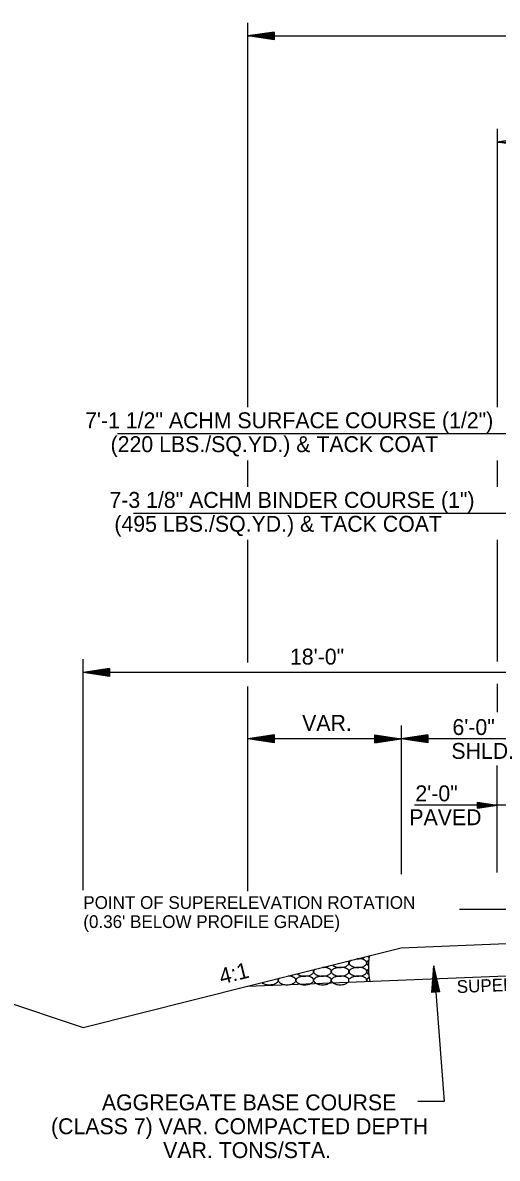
# Model space of a CAD drawing. Extents: x 2263886 to 2266026, y -3122850 to -3121850.
# Drawn here: x 2265563.48 to 2265581.37, y -3122515.03 to -3122472.22 of the extents above; entities that cross this region are included whole.
import ezdxf

# ---------------------------------------------------------------- set-up
doc = ezdxf.new("R2010")
doc.units = 0
doc.layers.add('R_Border Prem', color=7, linetype='Continuous')

msp = doc.modelspace()

# ---------------------------------------------------------------- linework, layer by layer
at = {"layer": 'R_Border Prem'}
for p, q in [((2265571.962, -3122486.717), (2265571.962, -3122472.217)), ((2265572.962, -3122472.567), (2265571.962, -3122472.717)), ((2265572.962, -3122472.567), (2265572.962, -3122472.867)), ((2265571.962, -3122472.717), (2265632.576, -3122472.717)), ((2265572.962, -3122472.867), (2265571.962, -3122472.717)), ((2265572.962, -3122472.592), (2265572.129, -3122472.717)), ((2265572.962, -3122472.842), (2265572.129, -3122472.717)), ((2265572.962, -3122472.617), (2265572.301, -3122472.717)), ((2265572.962, -3122472.816), (2265572.301, -3122472.717)), ((2265572.962, -3122472.642), (2265572.467, -3122472.717)), ((2265572.962, -3122472.791), (2265572.467, -3122472.717)), ((2265572.962, -3122472.668), (2265572.637, -3122472.717)), ((2265572.962, -3122472.766), (2265572.637, -3122472.717)), ((2265572.962, -3122472.693), (2265572.804, -3122472.717)), ((2265572.962, -3122472.74), (2265572.804, -3122472.717)), ((2265581.369, -3122476.217), (2265581.369, -3122486.717)), ((2265582.369, -3122476.567), (2265581.369, -3122476.717)), ((2265581.369, -3122476.717), (2265622.13, -3122476.717)), ((2265582.369, -3122476.867), (2265581.369, -3122476.717)), ((2265583.623, -3122487.72), (2265567.047, -3122487.72)), ((2265571.962, -3122489.717), (2265571.962, -3122488.717)), ((2265581.369, -3122488.717), (2265581.369, -3122489.717)), ((2265583.518, -3122490.72), (2265567.654, -3122490.72)), ((2265571.962, -3122496.338), (2265571.962, -3122491.717)), ((2265581.369, -3122491.717), (2265581.369, -3122494.717)), ((2265581.369, -3122494.717), (2265581.369, -3122496.297)), ((2265565.75, -3122504.917), (2265565.75, -3122496.217)), ((2265566.75, -3122496.567), (2265565.75, -3122496.717)), ((2265566.75, -3122496.567), (2265566.75, -3122496.867)), ((2265583.75, -3122496.717), (2265565.75, -3122496.717)), ((2265566.75, -3122496.867), (2265565.75, -3122496.717)), ((2265566.75, -3122496.592), (2265565.917, -3122496.717)), ((2265566.75, -3122496.842), (2265565.917, -3122496.717)), ((2265566.75, -3122496.617), (2265566.089, -3122496.717)), ((2265566.75, -3122496.816), (2265566.089, -3122496.717)), ((2265566.75, -3122496.642), (2265566.255, -3122496.717)), ((2265566.75, -3122496.791), (2265566.255, -3122496.717)), ((2265566.75, -3122496.668), (2265566.425, -3122496.717)), ((2265566.75, -3122496.766), (2265566.425, -3122496.717)), ((2265566.75, -3122496.693), (2265566.592, -3122496.717)), ((2265566.75, -3122496.74), (2265566.592, -3122496.717)), ((2265571.962, -3122504.954), (2265571.962, -3122497.248)), ((2265581.369, -3122497.137), (2265581.369, -3122498.217)), ((2265572.962, -3122499.067), (2265571.962, -3122499.217)), ((2265572.962, -3122499.092), (2265572.129, -3122499.217)), ((2265572.962, -3122499.117), (2265572.301, -3122499.217)), ((2265572.962, -3122499.067), (2265572.962, -3122499.367)), ((2265576.75, -3122499.067), (2265577.75, -3122499.217)), ((2265576.75, -3122499.367), (2265576.75, -3122499.067)), ((2265576.75, -3122499.092), (2265577.583, -3122499.217)), ((2265576.75, -3122499.117), (2265577.411, -3122499.217)), ((2265577.75, -3122498.717), (2265577.75, -3122504.317)), ((2265578.75, -3122499.067), (2265577.75, -3122499.217)), ((2265578.75, -3122499.092), (2265577.917, -3122499.217)), ((2265578.75, -3122499.117), (2265578.089, -3122499.217)), ((2265578.75, -3122499.067), (2265578.75, -3122499.367)), ((2265572.962, -3122499.367), (2265571.962, -3122499.217)), ((2265577.75, -3122499.217), (2265571.962, -3122499.217)), ((2265572.962, -3122499.342), (2265572.129, -3122499.217)), ((2265572.962, -3122499.316), (2265572.301, -3122499.217)), ((2265572.962, -3122499.142), (2265572.467, -3122499.217)), ((2265572.962, -3122499.291), (2265572.467, -3122499.217)), ((2265572.962, -3122499.168), (2265572.637, -3122499.217)), ((2265572.962, -3122499.266), (2265572.637, -3122499.217)), ((2265572.962, -3122499.193), (2265572.804, -3122499.217)), ((2265572.962, -3122499.24), (2265572.804, -3122499.217)), ((2265576.75, -3122499.142), (2265577.244, -3122499.217)), ((2265576.75, -3122499.168), (2265577.075, -3122499.217)), ((2265576.75, -3122499.193), (2265576.908, -3122499.217)), ((2265576.75, -3122499.367), (2265577.75, -3122499.217)), ((2265576.75, -3122499.265), (2265577.075, -3122499.217)), ((2265576.75, -3122499.316), (2265577.411, -3122499.217)), ((2265576.75, -3122499.342), (2265577.583, -3122499.217)), ((2265576.75, -3122499.291), (2265577.244, -3122499.217)), ((2265576.75, -3122499.24), (2265576.908, -3122499.217)), ((2265578.75, -3122499.367), (2265577.75, -3122499.217)), ((2265583.75, -3122499.217), (2265577.75, -3122499.217)), ((2265578.75, -3122499.342), (2265577.917, -3122499.217)), ((2265578.75, -3122499.316), (2265578.089, -3122499.217)), ((2265578.75, -3122499.142), (2265578.255, -3122499.217)), ((2265578.75, -3122499.291), (2265578.255, -3122499.217)), ((2265578.75, -3122499.168), (2265578.425, -3122499.217)), ((2265578.75, -3122499.266), (2265578.425, -3122499.217)), ((2265578.75, -3122499.193), (2265578.592, -3122499.217)), ((2265578.75, -3122499.24), (2265578.592, -3122499.217)), ((2265581.369, -3122504.251), (2265581.369, -3122500.217)), ((2265580.619, -3122501.604), (2265581.369, -3122501.717)), ((2265580.619, -3122501.829), (2265580.619, -3122501.604)), ((2265580.619, -3122501.623), (2265581.244, -3122501.717)), ((2265580.619, -3122501.642), (2265581.115, -3122501.717)), ((2265580.619, -3122501.661), (2265580.99, -3122501.717)), ((2265580.619, -3122501.68), (2265580.863, -3122501.717)), ((2265580.619, -3122501.699), (2265580.738, -3122501.717)), ((2265583.75, -3122501.717), (2265578.242, -3122501.717)), ((2265580.619, -3122501.829), (2265581.369, -3122501.717)), ((2265580.619, -3122501.753), (2265580.863, -3122501.717)), ((2265580.619, -3122501.791), (2265581.115, -3122501.717)), ((2265580.619, -3122501.81), (2265581.244, -3122501.717)), ((2265580.619, -3122501.773), (2265580.99, -3122501.717)), ((2265580.619, -3122501.734), (2265580.738, -3122501.717)), ((2265582.009, -3122505.651), (2265579.95, -3122505.651)), ((2265555.75, -3122506.763), (2265565.75, -3122510.097)), ((2265572.105, -3122508.508), (2265577.75, -3122507.097)), ((2265577.75, -3122507.097), (2265583.745, -3122506.857)), ((2265571.962, -3122508.544), (2265590.987, -3122507.782)), ((2265578.899, -3122508.782), (2265578.971, -3122507.774)), ((2265578.924, -3122508.78), (2265578.984, -3122507.94)), ((2265578.949, -3122508.778), (2265578.997, -3122508.112)), ((2265578.971, -3122507.774), (2265579.368, -3122512.886)), ((2265579.198, -3122508.759), (2265578.971, -3122507.774)), ((2265579.173, -3122508.761), (2265578.984, -3122507.94)), ((2265579.147, -3122508.763), (2265578.997, -3122508.112)), ((2265565.75, -3122510.097), (2265572.105, -3122508.508)), ((2265578.974, -3122508.777), (2265579.01, -3122508.278)), ((2265578.999, -3122508.775), (2265579.023, -3122508.447)), ((2265579.123, -3122508.765), (2265579.01, -3122508.278)), ((2265579.097, -3122508.767), (2265579.023, -3122508.447)), ((2265579.198, -3122508.759), (2265578.899, -3122508.782)), ((2265579.025, -3122508.773), (2265579.036, -3122508.613)), ((2265579.072, -3122508.769), (2265579.036, -3122508.613)), ((2265579.368, -3122512.886), (2265578.368, -3122512.886))]:
    msp.add_line(p, q, dxfattribs=at)
msp.add_arc((2265579.507, -3122507.797), 3, 172.4161, 190.8159, dxfattribs=at)
for points in [[(2265575.153, -3122507.746), (2265575.159, -3122507.75), (2265575.172, -3122507.759), (2265575.184, -3122507.778), (2265575.211, -3122507.783), (2265575.246, -3122507.804), (2265575.308, -3122507.82), (2265575.388, -3122507.837), (2265575.483, -3122507.836), (2265575.581, -3122507.822), (2265575.671, -3122507.798), (2265575.73, -3122507.752), (2265575.772, -3122507.716), (2265575.777, -3122507.677), (2265575.778, -3122507.644), (2265575.77, -3122507.616), (2265575.759, -3122507.602), (2265575.753, -3122507.596), (2265575.753, -3122507.596)], [(2265575.804, -3122507.607), (2265575.798, -3122507.613), (2265575.79, -3122507.628), (2265575.784, -3122507.651), (2265575.774, -3122507.672), (2265575.784, -3122507.696), (2265575.793, -3122507.717), (2265575.812, -3122507.74), (2265575.837, -3122507.755), (2265575.852, -3122507.778), (2265575.879, -3122507.783), (2265575.913, -3122507.804), (2265575.976, -3122507.82), (2265576.056, -3122507.837), (2265576.151, -3122507.836), (2265576.249, -3122507.822), (2265576.339, -3122507.798), (2265576.398, -3122507.752), (2265576.44, -3122507.716), (2265576.445, -3122507.677), (2265576.445, -3122507.644), (2265576.438, -3122507.616), (2265576.421, -3122507.596), (2265576.404, -3122507.58), (2265576.378, -3122507.569), (2265576.355, -3122507.55), (2265576.323, -3122507.539), (2265576.283, -3122507.519), (2265576.216, -3122507.515), (2265576.146, -3122507.51), (2265576.096, -3122507.514), (2265576.075, -3122507.515), (2265576.074, -3122507.515)], [(2265575.855, -3122507.57), (2265575.853, -3122507.571), (2265575.839, -3122507.58), (2265575.821, -3122507.596), (2265575.803, -3122507.608), (2265575.798, -3122507.613)], [(2265576.1, -3122507.509), (2265576.116, -3122507.509), (2265576.165, -3122507.507), (2265576.249, -3122507.496), (2265576.329, -3122507.473), (2265576.369, -3122507.447), (2265576.38, -3122507.439)], [(2265576.472, -3122507.607), (2265576.466, -3122507.613), (2265576.458, -3122507.628), (2265576.452, -3122507.651), (2265576.441, -3122507.672), (2265576.452, -3122507.696), (2265576.461, -3122507.717), (2265576.48, -3122507.74), (2265576.498, -3122507.752), (2265576.508, -3122507.761), (2265576.508, -3122507.761)], [(2265576.516, -3122507.575), (2265576.504, -3122507.582), (2265576.488, -3122507.596), (2265576.471, -3122507.608), (2265576.466, -3122507.613)], [(2265576.481, -3122507.414), (2265576.489, -3122507.42), (2265576.505, -3122507.43), (2265576.518, -3122507.446), (2265576.527, -3122507.451), (2265576.528, -3122507.451)], [(2265573.512, -3122508.156), (2265573.533, -3122508.153), (2265573.585, -3122508.145), (2265573.633, -3122508.131), (2265573.661, -3122508.119)], [(2265573.825, -3122508.078), (2265573.828, -3122508.08), (2265573.838, -3122508.087), (2265573.849, -3122508.104), (2265573.876, -3122508.11), (2265573.91, -3122508.13), (2265573.972, -3122508.146), (2265574.053, -3122508.163), (2265574.147, -3122508.162), (2265574.246, -3122508.148), (2265574.335, -3122508.124), (2265574.395, -3122508.078), (2265574.436, -3122508.042), (2265574.441, -3122508.003), (2265574.442, -3122507.97), (2265574.435, -3122507.944), (2265574.426, -3122507.932), (2265574.423, -3122507.928)], [(2265574.469, -3122507.934), (2265574.462, -3122507.939), (2265574.455, -3122507.954), (2265574.448, -3122507.977), (2265574.438, -3122507.998), (2265574.448, -3122508.022), (2265574.457, -3122508.043), (2265574.476, -3122508.067), (2265574.501, -3122508.081), (2265574.517, -3122508.104), (2265574.543, -3122508.11), (2265574.578, -3122508.13), (2265574.64, -3122508.146), (2265574.72, -3122508.163), (2265574.815, -3122508.162), (2265574.913, -3122508.148), (2265575.003, -3122508.124), (2265575.062, -3122508.078), (2265575.104, -3122508.042), (2265575.109, -3122508.003), (2265575.11, -3122507.97), (2265575.102, -3122507.942), (2265575.085, -3122507.922), (2265575.068, -3122507.906), (2265575.042, -3122507.895), (2265575.02, -3122507.877), (2265574.987, -3122507.865), (2265574.947, -3122507.845), (2265574.881, -3122507.841), (2265574.824, -3122507.836), (2265574.789, -3122507.838), (2265574.782, -3122507.839)], [(2265574.501, -3122507.909), (2265574.493, -3122507.914), (2265574.48, -3122507.925), (2265574.467, -3122507.934), (2265574.463, -3122507.94)], [(2265574.799, -3122507.834), (2265574.804, -3122507.834), (2265574.841, -3122507.832), (2265574.913, -3122507.822), (2265574.985, -3122507.801), (2265575.021, -3122507.781), (2265575.027, -3122507.777)], [(2265575.136, -3122507.934), (2265575.13, -3122507.939), (2265575.123, -3122507.954), (2265575.116, -3122507.977), (2265575.106, -3122507.998), (2265575.116, -3122508.022), (2265575.125, -3122508.043), (2265575.144, -3122508.067), (2265575.169, -3122508.081), (2265575.184, -3122508.104), (2265575.211, -3122508.11), (2265575.246, -3122508.13), (2265575.308, -3122508.146), (2265575.388, -3122508.163), (2265575.483, -3122508.162), (2265575.581, -3122508.148), (2265575.671, -3122508.124), (2265575.73, -3122508.078), (2265575.772, -3122508.042), (2265575.777, -3122508.003), (2265575.778, -3122507.97), (2265575.77, -3122507.942), (2265575.753, -3122507.922), (2265575.736, -3122507.906), (2265575.71, -3122507.895), (2265575.687, -3122507.877), (2265575.655, -3122507.865), (2265575.615, -3122507.845), (2265575.549, -3122507.841), (2265575.478, -3122507.836), (2265575.408, -3122507.843), (2265575.353, -3122507.843), (2265575.306, -3122507.857), (2265575.261, -3122507.864), (2265575.218, -3122507.879), (2265575.179, -3122507.901), (2265575.153, -3122507.922), (2265575.135, -3122507.934), (2265575.13, -3122507.94)], [(2265575.804, -3122507.934), (2265575.798, -3122507.939), (2265575.79, -3122507.954), (2265575.784, -3122507.977), (2265575.774, -3122507.998), (2265575.784, -3122508.022), (2265575.793, -3122508.043), (2265575.812, -3122508.067), (2265575.837, -3122508.081), (2265575.852, -3122508.104), (2265575.879, -3122508.11), (2265575.913, -3122508.13), (2265575.976, -3122508.146), (2265576.056, -3122508.163), (2265576.151, -3122508.162), (2265576.249, -3122508.148), (2265576.339, -3122508.124), (2265576.398, -3122508.078), (2265576.44, -3122508.042), (2265576.445, -3122508.003), (2265576.445, -3122507.97), (2265576.438, -3122507.942), (2265576.421, -3122507.922), (2265576.404, -3122507.906), (2265576.378, -3122507.895), (2265576.355, -3122507.877), (2265576.323, -3122507.865), (2265576.283, -3122507.845), (2265576.216, -3122507.841), (2265576.146, -3122507.836), (2265576.076, -3122507.843), (2265576.021, -3122507.843), (2265575.974, -3122507.857), (2265575.929, -3122507.864), (2265575.886, -3122507.879), (2265575.847, -3122507.901), (2265575.821, -3122507.922), (2265575.803, -3122507.934), (2265575.798, -3122507.94)], [(2265576.472, -3122507.934), (2265576.466, -3122507.939), (2265576.458, -3122507.954), (2265576.452, -3122507.977), (2265576.441, -3122507.998), (2265576.452, -3122508.022), (2265576.461, -3122508.043), (2265576.48, -3122508.067), (2265576.504, -3122508.081), (2265576.517, -3122508.096), (2265576.523, -3122508.101)], [(2265576.51, -3122507.905), (2265576.5, -3122507.911), (2265576.486, -3122507.923), (2265576.471, -3122507.934), (2265576.466, -3122507.94)], [(2265572.497, -3122508.41), (2265572.497, -3122508.41), (2265572.504, -3122508.416), (2265572.513, -3122508.431), (2265572.54, -3122508.436), (2265572.574, -3122508.456), (2265572.636, -3122508.473), (2265572.717, -3122508.489), (2265572.812, -3122508.488), (2265572.91, -3122508.475), (2265573, -3122508.45), (2265573.059, -3122508.404), (2265573.101, -3122508.368), (2265573.105, -3122508.33), (2265573.106, -3122508.296), (2265573.1, -3122508.274), (2265573.093, -3122508.263), (2265573.092, -3122508.261)], [(2265573.133, -3122508.26), (2265573.127, -3122508.265), (2265573.119, -3122508.28), (2265573.113, -3122508.304), (2265573.102, -3122508.324), (2265573.112, -3122508.348), (2265573.122, -3122508.369), (2265573.141, -3122508.393), (2265573.165, -3122508.407), (2265573.181, -3122508.431), (2265573.208, -3122508.436), (2265573.242, -3122508.456), (2265573.304, -3122508.473), (2265573.385, -3122508.489), (2265573.479, -3122508.488), (2265573.578, -3122508.475), (2265573.667, -3122508.45), (2265573.727, -3122508.404), (2265573.769, -3122508.368), (2265573.773, -3122508.33), (2265573.774, -3122508.296), (2265573.766, -3122508.268), (2265573.75, -3122508.249), (2265573.732, -3122508.232), (2265573.706, -3122508.221), (2265573.684, -3122508.203), (2265573.651, -3122508.191), (2265573.611, -3122508.171), (2265573.55, -3122508.168), (2265573.506, -3122508.163), (2265573.482, -3122508.163)], [(2265573.149, -3122508.247), (2265573.147, -3122508.248), (2265573.139, -3122508.254), (2265573.131, -3122508.26), (2265573.127, -3122508.266)], [(2265573.801, -3122508.26), (2265573.794, -3122508.265), (2265573.787, -3122508.28), (2265573.78, -3122508.304), (2265573.77, -3122508.324), (2265573.78, -3122508.348), (2265573.79, -3122508.369), (2265573.809, -3122508.393), (2265573.833, -3122508.407), (2265573.849, -3122508.431), (2265573.876, -3122508.436), (2265573.91, -3122508.456), (2265573.972, -3122508.473), (2265574.053, -3122508.489), (2265574.147, -3122508.488), (2265574.246, -3122508.475), (2265574.335, -3122508.45), (2265574.395, -3122508.404), (2265574.436, -3122508.368), (2265574.441, -3122508.33), (2265574.442, -3122508.296), (2265574.434, -3122508.268), (2265574.418, -3122508.249), (2265574.4, -3122508.232), (2265574.374, -3122508.221), (2265574.352, -3122508.203), (2265574.319, -3122508.191), (2265574.279, -3122508.171), (2265574.213, -3122508.167), (2265574.143, -3122508.162), (2265574.072, -3122508.169), (2265574.018, -3122508.17), (2265573.971, -3122508.183), (2265573.925, -3122508.19), (2265573.882, -3122508.206), (2265573.843, -3122508.227), (2265573.817, -3122508.248), (2265573.799, -3122508.26), (2265573.795, -3122508.266)], [(2265574.469, -3122508.26), (2265574.462, -3122508.265), (2265574.455, -3122508.28), (2265574.448, -3122508.304), (2265574.438, -3122508.324), (2265574.448, -3122508.348), (2265574.457, -3122508.369), (2265574.476, -3122508.393), (2265574.501, -3122508.407), (2265574.517, -3122508.431), (2265574.543, -3122508.436), (2265574.578, -3122508.456), (2265574.64, -3122508.473), (2265574.72, -3122508.489), (2265574.815, -3122508.488), (2265574.913, -3122508.475), (2265575.003, -3122508.45), (2265575.062, -3122508.404), (2265575.104, -3122508.368), (2265575.109, -3122508.33), (2265575.11, -3122508.296), (2265575.102, -3122508.268), (2265575.085, -3122508.249), (2265575.068, -3122508.232), (2265575.042, -3122508.221), (2265575.02, -3122508.203), (2265574.987, -3122508.191), (2265574.947, -3122508.171), (2265574.881, -3122508.167), (2265574.81, -3122508.162), (2265574.74, -3122508.169), (2265574.686, -3122508.17), (2265574.639, -3122508.183), (2265574.593, -3122508.19), (2265574.55, -3122508.206), (2265574.511, -3122508.227), (2265574.485, -3122508.248), (2265574.467, -3122508.26), (2265574.463, -3122508.266)], [(2265575.136, -3122508.26), (2265575.13, -3122508.265), (2265575.123, -3122508.28), (2265575.116, -3122508.304), (2265575.106, -3122508.324), (2265575.116, -3122508.348), (2265575.125, -3122508.369), (2265575.144, -3122508.393), (2265575.169, -3122508.407), (2265575.184, -3122508.431), (2265575.211, -3122508.436), (2265575.246, -3122508.456), (2265575.308, -3122508.473), (2265575.388, -3122508.489), (2265575.483, -3122508.488), (2265575.581, -3122508.475), (2265575.671, -3122508.45), (2265575.73, -3122508.404), (2265575.772, -3122508.368), (2265575.777, -3122508.33), (2265575.778, -3122508.296), (2265575.77, -3122508.268), (2265575.753, -3122508.249), (2265575.736, -3122508.232), (2265575.71, -3122508.221), (2265575.687, -3122508.203), (2265575.655, -3122508.191), (2265575.615, -3122508.171), (2265575.549, -3122508.167), (2265575.478, -3122508.162), (2265575.408, -3122508.169), (2265575.353, -3122508.17), (2265575.306, -3122508.183), (2265575.261, -3122508.19), (2265575.218, -3122508.206), (2265575.179, -3122508.227), (2265575.153, -3122508.248), (2265575.135, -3122508.26), (2265575.13, -3122508.266)], [(2265576.436, -3122508.365), (2265576.436, -3122508.363), (2265576.442, -3122508.352), (2265576.445, -3122508.33), (2265576.445, -3122508.296), (2265576.438, -3122508.268), (2265576.421, -3122508.249), (2265576.404, -3122508.232), (2265576.378, -3122508.221), (2265576.355, -3122508.203), (2265576.323, -3122508.191), (2265576.283, -3122508.171), (2265576.216, -3122508.167), (2265576.146, -3122508.162), (2265576.076, -3122508.169), (2265576.021, -3122508.17), (2265575.974, -3122508.183), (2265575.929, -3122508.19), (2265575.886, -3122508.206), (2265575.847, -3122508.227), (2265575.821, -3122508.248), (2265575.803, -3122508.26), (2265575.798, -3122508.266)], [(2265576.472, -3122508.26), (2265576.466, -3122508.265), (2265576.458, -3122508.28), (2265576.452, -3122508.304), (2265576.441, -3122508.324), (2265576.451, -3122508.346), (2265576.456, -3122508.357), (2265576.459, -3122508.364)], [(2265576.537, -3122508.215), (2265576.531, -3122508.218), (2265576.511, -3122508.229), (2265576.488, -3122508.248), (2265576.471, -3122508.26), (2265576.466, -3122508.266)]]:
    msp.add_open_spline(points, degree=3, dxfattribs=at)

# ---------------------------------------------------------------- texts
for s, height, p in [('7\'-1 1/2" ACHM SURFACE COURSE (1/2")', 0.6, (2265565.827, -3122487.507)), ('(220 LBS./SQ.YD.) & TACK COAT', 0.6, (2265566.789, -3122488.407)), ('7-3 1/8" ACHM BINDER COURSE (1")', 0.6, (2265566.745, -3122490.509)), ('(495 LBS./SQ.YD.) & TACK COAT', 0.6, (2265566.931, -3122491.409)), ('18\'-0"', 0.6, (2265573.552, -3122496.417)), ('6\'-0"', 0.6, (2265579.678, -3122499.072)), ('SHLD.', 0.6, (2265579.638, -3122499.972)), ('2\'-0"', 0.6, (2265578.281, -3122501.572)), ('PAVED', 0.6, (2265578.054, -3122502.472)), ('POINT OF SUPERELEVATION ROTATION', 0.48, (2265565.76, -3122505.629)), ("(0.36' BELOW PROFILE GRADE)", 0.48, (2265565.76, -3122506.349)), ('AGGREGATE BASE COURSE', 0.6, (2265566.46, -3122513.223)), ('(CLASS 7) VAR. COMPACTED DEPTH', 0.6, (2265564.542, -3122514.123)), ('VAR. TONS/STA.', 0.6, (2265568.77, -3122515.023))]:
    msp.add_text(s, height=height, dxfattribs=at).set_placement(p)
for s, height, rotation, p in [('VAR.', 0.6, 0, (2265574.011, -3122498.917)), ('4:1', 0.6, 14.0362, (2265570.971, -3122508.482)), ('SUPER. SLOPE', 0.48, 2.291, (2265579.85, -3122508.802))]:
    msp.add_text(s, height=height, rotation=rotation, dxfattribs=at).set_placement(p)

doc.saveas('drawing.dxf')
